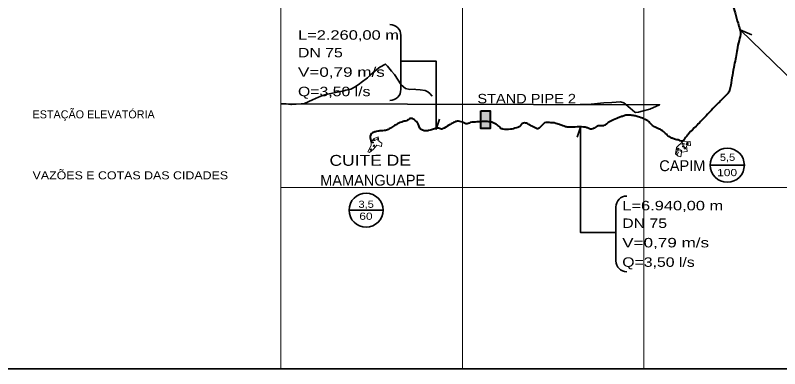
# Model space of a CAD drawing. Extents: x -4 to 42046, y -3 to 29697.
# Drawn here: x 31133 to 37843, y 10020 to 13120 of the extents above; entities that cross this region are included whole.
import ezdxf
from ezdxf.enums import TextEntityAlignment as Align

# ---------------------------------------------------------------- set-up
doc = ezdxf.new("R2010")
doc.units = 0
doc.header["$LTSCALE"] = 32
doc.linetypes.add('DOT_DASHED', pattern=[7.7, 5, -1.2, 0.3, -1.2])
for name, color, linetype, lineweight in [('1', 7, 'DOT_DASHED', 13), ('3', 7, 'Continuous', 35), ('6', 7, 'Continuous', 40), ('63', 7, 'Continuous', 25), ('8', 7, 'Continuous', 35), ('9', 7, 'Continuous', 40)]:
    doc.layers.add(name, color=color, linetype=linetype, lineweight=lineweight)

msp = doc.modelspace()

# ---------------------------------------------------------------- hatches: boundary and pattern name
at = {"layer": '8'}
msp.add_hatch(color=256, dxfattribs=at).paths.add_polyline_path([(35219.12, 12281.47), (35300.75, 12281.47), (35300.75, 12126.98), (35219.12, 12126.98)])

# ---------------------------------------------------------------- linework, layer by layer
at = {"layer": '1', "linetype": 'Continuous'}
for points in [[(34228.84, 11921.35), (34257.51, 11977.51), (34256.61, 12009.95), (34284.16, 12039.27), (34319.76, 12052.59), (34323.48, 12016.15), (34349.56, 11997.41), (34346.44, 11970.16), (34305.56, 11981.66), (34278.03, 11946.33), (34242.07, 11916.99)], [(34277.81, 12020.42), (34277.79, 12026.09), (34291.01, 12026.12), (34291.02, 12020.46)], [(34306.21, 12029.72), (34310.99, 12040.55), (34321.83, 12035.78), (34317.05, 12024.95)], [(34251.23, 11935.04), (34247.21, 11939.03), (34256.4, 11948.26), (34260.42, 11944.27)], [(34266.25, 12000.77), (34266.23, 12006.43), (34278.65, 12006.46), (34278.67, 12000.8)], [(34274.75, 11970.35), (34279.92, 11982.38), (34287.36, 11979.19), (34282.19, 11967.16)], [(36941.05, 11943.61), (36952.77, 11953.71), (36960.63, 11944.62), (36948.91, 11934.52)], [(36986.58, 11985.03), (36990.56, 11999.48), (37005.03, 11995.5), (37001.04, 11981.05)], [(36990.66, 11966.58), (37004.42, 11966.62), (37004.4, 11973), (36990.64, 11972.96)], [(37005.82, 11947.49), (37005.79, 11958.91), (37017.21, 11958.94), (37017.25, 11947.53)], [(37021.48, 11987.48), (37021.46, 11992.86), (37038.92, 11992.91), (37038.93, 11987.54)], [(37026.82, 11997.57), (37026.8, 12002.94), (37039.9, 12002.98), (37039.91, 11997.61)], [(36937.12, 11911.71), (36941.11, 11924.48), (36953.89, 11920.49), (36949.9, 11907.72)], [(36967.61, 11929.93), (36973.29, 11939.34), (36982.71, 11933.67), (36977.04, 11924.25)]]:
    msp.add_lwpolyline(points, close=True, dxfattribs=at)
msp.add_lwpolyline([(36947.59, 11896.51), (36928.75, 11906.16), (36936.47, 11960.8), (36995.17, 12016.2), (37056.48, 12011.53), (37060.22, 11977.56), (37026.21, 11973.82), (37031.62, 11924.69), (36982.44, 11919.28), (36974.34, 11879.6), (36951.27, 11884.3), (36928.75, 11906.16)], dxfattribs=at)
at = {"layer": '3'}
for points in [[(36090.67, 12337.38), (36162.74, 12337.38), (36270.48, 12350.6), (36300.11, 12350.85), (36370.12, 12353.91), (36446.34, 12359.9), (36473.62, 12351.07), (36531, 12305.56), (36570.96, 12269.05), (36577.82, 12266.49), (36604.43, 12269.31), (36635.35, 12280.28), (36703.19, 12297.86), (36789.18, 12335.72), (33469.07, 12342.95), (33508.53, 12344.64), (33552.38, 12336.48), (33558.75, 12336.36), (33643.86, 12344.67), (33672.99, 12345.99), (33742.52, 12377.76), (33795.07, 12400.67), (33824.04, 12413.91), (33841.93, 12420.63), (33860.1, 12426.55), (34016.14, 12458.5), (34034.63, 12463.31), (34078.16, 12473.01), (34118.05, 12492.95), (34154.54, 12518.55), (34170.09, 12529.66), (34225.25, 12572.85), (34249.44, 12593.55), (34292.33, 12631.56), (34334.37, 12665.67), (34381.7, 12691.96), (34400.36, 12674.63), (34435.71, 12631.16), (34461.14, 12600.97), (34519.47, 12509.8)], [(36090.67, 12337.38), (36162.74, 12337.38), (36270.48, 12350.6), (36300.11, 12350.85), (36370.12, 12353.91), (36446.34, 12359.9), (36473.62, 12351.07), (36531, 12305.56), (36570.96, 12269.05), (36577.82, 12266.49), (36604.43, 12269.31), (36635.35, 12280.28), (36703.19, 12297.86), (36789.18, 12335.72), (33469.07, 12342.95), (33508.53, 12344.64), (33552.38, 12336.48), (33558.75, 12336.36), (33643.86, 12344.67), (33672.99, 12345.99), (33742.52, 12377.76), (33795.07, 12400.67), (33824.04, 12413.91), (33841.93, 12420.63), (33860.1, 12426.55), (34016.14, 12458.5), (34034.63, 12463.31), (34078.16, 12473.01), (34118.05, 12492.95), (34154.54, 12518.55), (34170.09, 12529.66), (34225.25, 12572.85), (34249.44, 12593.55), (34292.33, 12631.56), (34334.37, 12665.67), (34381.7, 12691.96), (34400.36, 12674.63), (34435.71, 12631.16), (34461.14, 12600.97), (34519.47, 12509.8)], [(34519.47, 12509.8), (34558.28, 12476.79), (34595.87, 12469.89), (34634.08, 12471.28), (34649.98, 12470.47), (34688.01, 12466.53), (34732, 12459.24), (34754.93, 12448.11), (34772.03, 12433.82), (34792.96, 12409.83)], [(34519.47, 12509.8), (34558.28, 12476.79), (34595.87, 12469.89), (34634.08, 12471.28), (34649.98, 12470.47), (34688.01, 12466.53), (34732, 12459.24), (34754.93, 12448.11), (34772.03, 12433.82), (34792.96, 12409.83)]]:
    msp.add_lwpolyline(points, dxfattribs=at)
at = {"layer": '6'}
for p, q in [((35864.29, 12175.21), (35859.88, 12175.33)), ((34247.39, 12047.79), (34256.61, 12009.95))]:
    msp.add_line(p, q, dxfattribs=at)
for points in [[(37388.59, 13346.26), (37427.93, 13218.17), (37450.7, 13140.3), (37477.17, 13050.5), (37493.3, 12996.04), (37498.18, 12976.54), (37499.55, 12969.64), (37485.73, 12897.94), (37470.56, 12818.38), (37444.11, 12683.26), (37412.66, 12506.42), (37403.58, 12461.37), (37401.48, 12454.75), (37389.27, 12437.29), (37366.5, 12413.37), (37344.72, 12391.46), (37326.68, 12372.25), (37314.05, 12359.13), (37280.52, 12325.61), (37185.56, 12226.97), (37108.82, 12147.79), (37045.3, 12082.37), (37021.69, 12053.47), (37000.96, 12025.99), (36995.12, 12017.71), (36960.08, 12023.74)], [(34718.3, 12109.44), (34697.36, 12116.98), (34685.18, 12129.09), (34678.31, 12145.57), (34666.55, 12173.31), (34639.8, 12199.58), (34613.67, 12215.42), (34585.89, 12207.1), (34575.91, 12198.73), (34556.19, 12192.16), (34537.25, 12188.09), (34489.5, 12166.55), (34461.78, 12153.05), (34427.61, 12131.16), (34399.61, 12116.04), (34382.61, 12110.32), (34333.04, 12105.89), (34295.75, 12098.7), (34269.51, 12089.49), (34253.38, 12073.25), (34247.38, 12047.73)], [(36650.19, 12210.68), (36600.35, 12230.58), (36565.49, 12238.45), (36526.75, 12244.49), (36499.84, 12244.41), (36470.12, 12236.18), (36439.67, 12225.16), (36425.74, 12219.26), (36371.45, 12198.41), (36347.58, 12184.88), (36329.23, 12172.07), (36316.42, 12160.8), (36303.44, 12153.21), (36295.08, 12150.53), (36250.92, 12150.4), (36213.45, 12130.78), (36192.35, 12122.27), (36173.88, 12123.98), (36150.82, 12133.82), (36121.56, 12139.97), (36046.46, 12139.75), (35976.77, 12139.54), (35962.13, 12142.94), (35940.03, 12151.31), (35909.67, 12160.9), (35889.04, 12167.53), (35864.29, 12175.21)], [(35859.88, 12175.33), (35823.46, 12178.86), (35779.45, 12175.42), (35754.04, 12153.71), (35730.56, 12128.82), (35722.05, 12123.68), (35718.86, 12123.67), (35708.1, 12127.35), (35660.68, 12151.18), (35621.39, 12172.33), (35585.4, 12172.22), (35564.83, 12148.94), (35556.9, 12141.14), (35543.51, 12135.67), (35519.23, 12128.87), (35505.06, 12124.15), (35480.82, 12120.9), (35413.04, 12120.69), (35401.43, 12125.33), (35386.62, 12138.21), (35370.26, 12153.88), (35354.01, 12163.76), (35327.51, 12177.43), (35278.4, 12187.62), (35154.1, 12182.22), (35125.74, 12178.47), (35092.13, 12167.43), (35082.6, 12170.18), (35058.2, 12181.8), (35013.72, 12191.33), (34980.61, 12179.91), (34939.03, 12156.98), (34882.03, 12123.47), (34873.99, 12121.56), (34857.78, 12126.51), (34840.21, 12130.85), (34804.05, 12120), (34785.95, 12114.59), (34761.68, 12108.25), (34730.4, 12106.05), (34716.67, 12109.8)], [(36961.77, 12023.7), (36919.08, 12034.53), (36893.8, 12043.41), (36869.71, 12057.22), (36841.52, 12082.89), (36815.18, 12105.37), (36789.1, 12120.48), (36767.82, 12129.86), (36744.86, 12141.43), (36726.65, 12152.14), (36713.5, 12164.5), (36693.94, 12186.18), (36673.25, 12199.27), (36651.53, 12209.83)]]:
    msp.add_spline(points, degree=3, dxfattribs=at)
at = {"layer": '63', "lineweight": 13}
for p, q in [((33464.65, 10019.66), (33464.65, 18929.66)), ((35057.45, 10019.66), (35057.45, 18929.66)), ((36650.26, 10019.66), (36650.26, 18929.66)), ((41110.1, 11610.73), (33464.65, 11610.73))]:
    msp.add_line(p, q, dxfattribs=at)
at = {"layer": '63', "lineweight": 35}
msp.add_lwpolyline([(41110.1, 10019.66), (23907.83, 10019.66), (23907.83, 18929.66)], dxfattribs=at)
at = {"layer": '8'}
for p, q in [((34517.75, 12469.5), (34517.75, 12942.89)), ((36404.66, 10965.14), (36404.66, 11438.52))]:
    msp.add_line(p, q, dxfattribs=at)
for points in [[(38291.17, 12521.52), (37982.43, 12521.52), (37494.5, 12991.71), (37598.13, 12948.82)], [(34517.75, 12718.16), (34826.49, 12718.16), (34826.49, 12120.65), (34858.15, 12209.71)], [(36404.66, 11213.79), (36095.93, 11213.79), (36095.93, 12139.48), (36064.26, 12050.42)]]:
    msp.add_lwpolyline(points, dxfattribs=at)
at = {"layer": '8', "lineweight": 40}
msp.add_lwpolyline([(35219.12, 12281.47), (35300.75, 12281.47), (35300.75, 12126.98), (35219.12, 12126.98)], close=True, dxfattribs=at)
at = {"layer": '8'}
for centre, major_axis, start_param, end_param in [((34422.19, 12942.89), (95.57, 0), 6.2831853, 7.8539816), ((34422.19, 12942.89), (95.57, 0), 6.2831853, 7.8539816), ((34422.19, 12942.89), (95.57, 0), 6.2831853, 7.8539816), ((34422.19, 12469.5), (95.57, 0), 4.712389, 6.2831853), ((36500.23, 11438.52), (-95.57, 0), 4.712389, 6.2831853), ((36500.23, 11438.52), (-95.57, 0), 4.712389, 6.2831853), ((36500.23, 11438.52), (-95.57, 0), 4.712389, 6.2831853), ((36500.23, 10965.14), (-95.57, 0), 6.2831853, 7.8539816)]:
    msp.add_ellipse(centre, major_axis=major_axis, ratio=0.998913, start_param=start_param, end_param=end_param, dxfattribs=at)
at = {"layer": '9', "lineweight": 35}
for p, q in [((37233.35, 11805.04), (37532.61, 11805.04)), ((34063.21, 11410.5), (34362.47, 11410.5))]:
    msp.add_line(p, q, dxfattribs=at)
for centre in [(37382.98, 11805.04), (34212.84, 11410.5)]:
    msp.add_circle(centre, 149.63, dxfattribs=at)

# ---------------------------------------------------------------- texts
at = {"layer": '63'}
msp.add_text('ESTAÇÃO ELEVATÓRIA', height=70.71, dxfattribs=at).set_placement((31285.21, 12215.77))
at = {"layer": '63', "width": 1.15}
msp.add_text('VAZÕES E COTAS DAS CIDADES', height=70.71, dxfattribs=at).set_placement((31285.21, 11680.75))
at = {"layer": '8'}
for s, width, p in [('L=2.260,00 m', 1.3, (33614.76, 12905.82)), ('DN 75', 1.25, (33614.76, 12751.33)), ('V=0,79 m/s', 1.35, (33614.76, 12580.74)), ('Q=3,50 l/s', 1.25, (33614.76, 12410.15)), ('STAND PIPE 2', 1.15, (35189.55, 12347.6)), ('L=6.940,00 m', 1.3, (36460.95, 11408.99)), ('DN 75', 1.25, (36460.95, 11254.5)), ('V=0,79 m/s', 1.35, (36460.95, 11083.91)), ('Q=3,50 l/s', 1.25, (36460.95, 10913.32))]:
    msp.add_text(s, height=82.98, dxfattribs=dict(at, width=width)).set_placement(p)
at = {"layer": '9'}
for s, height, width, p in [('CUITE DE ', 95.46, 1.2, (34270.26, 11800.39)), ('5,5', 63, 1.15, (37385.07, 11842.75)), ('100', 63, 1.25, (37381.37, 11708.8)), ('3,5', 63, 1.15, (34213.08, 11431.01)), ('60', 63, 1.25, (34211.23, 11325.92))]:
    msp.add_text(s, height=height, rotation=0.17, dxfattribs=dict(at, width=width)).set_placement(p, align=Align.CENTER)
msp.add_text('CAPIM', height=95.46, rotation=0.17, dxfattribs=at).set_placement((36786.39, 11752.45))
msp.add_text('MAMANGUAPE', height=95.46, rotation=0.17, dxfattribs=at).set_placement((34270.78, 11625.37), align=Align.CENTER)

doc.saveas('drawing.dxf')
